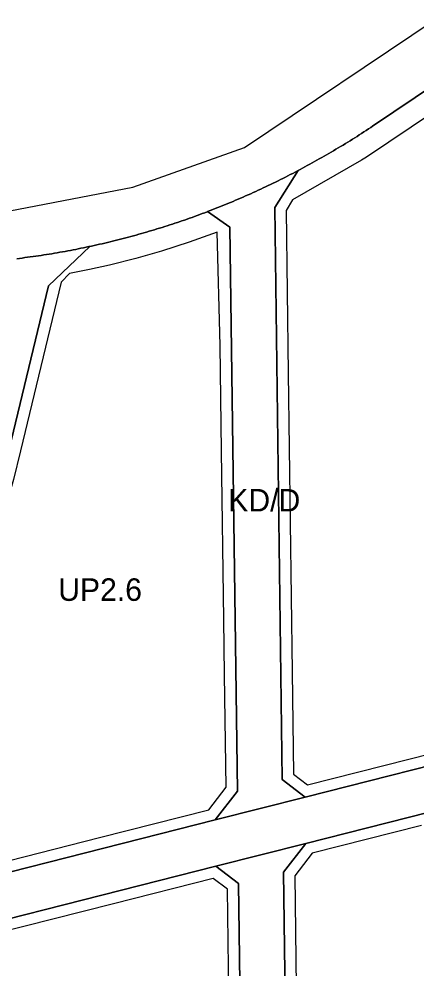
# Model space of a CAD drawing. Extents: x -297746 to -295403, y 27112 to 28877.
# Drawn here: x -296833.6 to -296657.1, y 27745.5 to 28167.1 of the extents above; entities that cross this region are included whole.
import ezdxf

# ---------------------------------------------------------------- set-up
doc = ezdxf.new("R2010")
doc.units = 0
for name, color, linetype in [('linie_rozgraniczajace', 7, 'Continuous'), ('linie_zabudowy_nieprzekraczalne', 7, 'Continuous'), ('oznaczenia_przeznaczen', 7, 'Continuous')]:
    doc.layers.add(name, color=color, linetype=linetype)

msp = doc.modelspace()

# ---------------------------------------------------------------- linework, layer by layer
at = {"layer": 'linie_rozgraniczajace'}
for points in [[(-297352.574, 28097.205), (-297275.154, 28075.397), (-297209.735, 28062.001), (-297116.494, 28056.361), (-297048.036, 28064.682), (-296954.075, 28076.102), (-296853.315, 28078.922), (-296783.197, 28092.318), (-296733.569, 28109.944), (-296648.599, 28167.051)], [(-296648.438, 28138.524), (-296676.764, 28119.432), (-296677.554, 28118.905), (-296678.571, 28118.231), (-296679.589, 28117.561), (-296680.61, 28116.894), (-296681.633, 28116.231), (-296682.659, 28115.57), (-296683.686, 28114.914), (-296684.716, 28114.26), (-296685.747, 28113.61), (-296686.781, 28112.963), (-296687.817, 28112.32), (-296688.855, 28111.68), (-296689.895, 28111.043), (-296690.938, 28110.41), (-296691.982, 28109.781), (-296693.028, 28109.154), (-296694.077, 28108.532), (-296695.127, 28107.912), (-296696.18, 28107.296), (-296697.234, 28106.684), (-296698.291, 28106.075), (-296699.349, 28105.469), (-296700.41, 28104.867), (-296701.472, 28104.269), (-296702.537, 28103.673), (-296703.603, 28103.082), (-296704.671, 28102.494), (-296705.742, 28101.909), (-296706.814, 28101.328), (-296707.888, 28100.751), (-296708.964, 28100.176), (-296709.827, 28099.719), (-296710.041, 28099.606), (-296711.121, 28099.039), (-296712.203, 28098.476), (-296713.286, 28097.916), (-296714.371, 28097.359), (-296715.458, 28096.807), (-296716.547, 28096.257), (-296717.638, 28095.712), (-296718.73, 28095.17), (-296719.824, 28094.631), (-296720.92, 28094.097), (-296722.018, 28093.565), (-296723.117, 28093.038), (-296724.218, 28092.514), (-296725.321, 28091.993), (-296726.426, 28091.476), (-296727.532, 28090.963), (-296728.64, 28090.454), (-296729.75, 28089.948), (-296730.861, 28089.445), (-296731.974, 28088.947), (-296733.088, 28088.452)], [(-296451.602, 27886.266), (-296706.72, 27821.429), (-296716.822, 27829.179), (-296720.16, 28083.326), (-296709.827, 28099.719), (-296708.964, 28100.176), (-296707.888, 28100.751), (-296706.814, 28101.328), (-296705.742, 28101.909), (-296704.671, 28102.494), (-296703.603, 28103.082), (-296702.537, 28103.673), (-296701.472, 28104.269), (-296700.41, 28104.867), (-296699.349, 28105.469), (-296698.291, 28106.075), (-296697.234, 28106.684), (-296696.18, 28107.296), (-296695.127, 28107.912), (-296694.077, 28108.532), (-296693.028, 28109.154), (-296691.982, 28109.781), (-296690.938, 28110.41), (-296689.895, 28111.043), (-296688.855, 28111.68), (-296687.817, 28112.32), (-296686.781, 28112.963), (-296685.747, 28113.61), (-296684.716, 28114.26), (-296683.686, 28114.914), (-296682.659, 28115.57), (-296681.633, 28116.231), (-296680.61, 28116.894), (-296679.589, 28117.561), (-296678.571, 28118.231), (-296677.554, 28118.905), (-296676.764, 28119.432), (-296648.438, 28138.524)], [(-296733.088, 28088.452), (-296734.204, 28087.961), (-296735.322, 28087.473), (-296736.441, 28086.989), (-296737.562, 28086.509), (-296738.685, 28086.032), (-296739.809, 28085.559), (-296740.934, 28085.09), (-296742.061, 28084.624), (-296743.19, 28084.162), (-296744.32, 28083.704), (-296745.452, 28083.25), (-296746.585, 28082.799), (-296747.72, 28082.352), (-296748.856, 28081.909), (-296749.993, 28081.469), (-296750.093, 28081.431), (-296751.216, 28081.007), (-296752.34, 28080.586), (-296753.465, 28080.169), (-296754.592, 28079.756), (-296755.72, 28079.347), (-296756.849, 28078.941), (-296757.98, 28078.539), (-296759.112, 28078.141), (-296760.245, 28077.747), (-296761.38, 28077.356), (-296762.164, 28077.089), (-296763.301, 28076.705), (-296764.439, 28076.324), (-296765.578, 28075.948), (-296766.719, 28075.575), (-296767.861, 28075.206), (-296769.004, 28074.841), (-296770.148, 28074.48), (-296771.293, 28074.122), (-296772.44, 28073.768), (-296773.588, 28073.419), (-296774.737, 28073.072), (-296775.887, 28072.73), (-296777.039, 28072.392), (-296778.191, 28072.057), (-296779.344, 28071.727), (-296780.499, 28071.4), (-296781.655, 28071.077), (-296782.812, 28070.758), (-296783.969, 28070.442), (-296785.128, 28070.131), (-296786.288, 28069.823), (-296787.449, 28069.52), (-296788.611, 28069.22), (-296789.774, 28068.924), (-296790.938, 28068.632), (-296792.103, 28068.344), (-296793.269, 28068.059), (-296794.435, 28067.779), (-296795.603, 28067.503), (-296796.772, 28067.23), (-296797.941, 28066.961), (-296799.112, 28066.696), (-296800.283, 28066.435), (-296801.455, 28066.178), (-296802.248, 28066.007), (-296802.628, 28065.925), (-296803.802, 28065.676), (-296804.977, 28065.431), (-296806.152, 28065.189), (-296807.328, 28064.952), (-296808.505, 28064.719), (-296809.683, 28064.489), (-296810.862, 28064.263), (-296812.041, 28064.041), (-296813.221, 28063.824), (-296814.402, 28063.61), (-296815.584, 28063.4), (-296816.766, 28063.194), (-296817.949, 28062.992), (-296819.132, 28062.794), (-296820.316, 28062.6), (-296821.501, 28062.409), (-296822.687, 28062.223), (-296823.873, 28062.041), (-296825.059, 28061.862), (-296826.247, 28061.688), (-296827.434, 28061.518), (-296828.623, 28061.351), (-296829.812, 28061.188), (-296831.001, 28061.03), (-296832.191, 28060.875), (-296833.382, 28060.725), (-296834.573, 28060.578)], [(-296840.945, 27963.7), (-296820.49, 28048.576), (-296802.248, 28066.007), (-296801.455, 28066.178), (-296800.283, 28066.435), (-296799.112, 28066.696), (-296797.941, 28066.961), (-296796.772, 28067.23), (-296795.603, 28067.503), (-296794.435, 28067.779), (-296793.269, 28068.059), (-296792.103, 28068.344), (-296790.938, 28068.632), (-296789.774, 28068.924), (-296788.611, 28069.22), (-296787.449, 28069.52), (-296786.288, 28069.823), (-296785.128, 28070.131), (-296783.969, 28070.442), (-296782.812, 28070.758), (-296781.655, 28071.077), (-296780.499, 28071.4), (-296779.344, 28071.727), (-296778.191, 28072.057), (-296777.039, 28072.392), (-296775.887, 28072.73), (-296774.737, 28073.072), (-296773.588, 28073.419), (-296772.44, 28073.768), (-296771.293, 28074.122), (-296770.148, 28074.48), (-296769.004, 28074.841), (-296767.861, 28075.206), (-296766.719, 28075.575), (-296765.578, 28075.948), (-296764.439, 28076.324), (-296763.301, 28076.705), (-296762.164, 28077.089), (-296761.38, 28077.356), (-296760.245, 28077.747), (-296759.112, 28078.141), (-296757.98, 28078.539), (-296756.849, 28078.941), (-296755.72, 28079.347), (-296754.592, 28079.756), (-296753.465, 28080.169), (-296752.34, 28080.586), (-296751.216, 28081.007), (-296750.093, 28081.431), (-296749.993, 28081.469), (-296740.047, 28074.586), (-296736.758, 27824.113), (-296746.59, 27811.296), (-296903.708, 27771.365)], [(-296834.573, 28060.578), (-296833.382, 28060.725), (-296832.191, 28060.875), (-296831.001, 28061.03), (-296829.812, 28061.188), (-296828.623, 28061.351), (-296827.434, 28061.518), (-296826.247, 28061.688), (-296825.059, 28061.862), (-296823.873, 28062.041), (-296822.687, 28062.223), (-296821.501, 28062.409), (-296820.316, 28062.6), (-296819.132, 28062.794), (-296817.949, 28062.992), (-296816.766, 28063.194), (-296815.584, 28063.4), (-296814.402, 28063.61), (-296813.221, 28063.824), (-296812.041, 28064.041), (-296810.862, 28064.263), (-296809.683, 28064.489), (-296808.505, 28064.719), (-296807.328, 28064.952), (-296806.152, 28065.189), (-296804.977, 28065.431), (-296803.802, 28065.676), (-296802.628, 28065.925), (-296802.248, 28066.007), (-296820.49, 28048.576), (-296840.945, 27963.7)], [(-297002.218, 27750.658), (-297000.74, 27748.463), (-296999.755, 27746.94), (-296998.73, 27747.216), (-296938.097, 27762.625), (-296922.224, 27766.659), (-296908.226, 27770.217), (-296903.708, 27771.365), (-296746.59, 27811.296), (-296706.72, 27821.429), (-296451.602, 27886.266)], [(-296434.505, 27869.975), (-296706.45, 27800.862), (-296746.32, 27790.729), (-296906.963, 27749.902), (-296939.511, 27741.63), (-296994.696, 27727.605), (-296995.426, 27722.859), (-296995.977, 27720.526), (-296996.722, 27717.999), (-296996.986, 27717.325), (-296988.793, 27710.975), (-297001.433, 27695.468), (-297009.248, 27701.525), (-297010.984, 27700.354), (-297012.53, 27699.459), (-297013.954, 27698.747), (-297015.744, 27697.933), (-297017.209, 27697.364), (-297018.714, 27696.855), (-297020.158, 27696.448), (-297021.212, 27696.201), (-297026.982, 27695.447)], [(-296732.893, 27529.874), (-296736.217, 27782.978), (-296746.32, 27790.729), (-296706.45, 27800.862), (-296716.282, 27788.045), (-296712.625, 27509.58)]]:
    msp.add_lwpolyline(points, dxfattribs=at)
for points in [[(-296746.59, 27811.296), (-296736.758, 27824.113), (-296740.047, 28074.586), (-296749.993, 28081.469), (-296748.856, 28081.909), (-296747.72, 28082.352), (-296746.585, 28082.799), (-296745.452, 28083.25), (-296744.32, 28083.704), (-296743.19, 28084.162), (-296742.061, 28084.624), (-296740.934, 28085.09), (-296739.809, 28085.559), (-296738.685, 28086.032), (-296737.562, 28086.509), (-296736.441, 28086.989), (-296735.322, 28087.473), (-296734.204, 28087.961), (-296733.088, 28088.452), (-296731.974, 28088.947), (-296730.861, 28089.445), (-296729.75, 28089.948), (-296728.64, 28090.454), (-296727.532, 28090.963), (-296726.426, 28091.476), (-296725.321, 28091.993), (-296724.218, 28092.514), (-296723.117, 28093.038), (-296722.018, 28093.565), (-296720.92, 28094.097), (-296719.824, 28094.631), (-296718.73, 28095.17), (-296717.638, 28095.712), (-296716.547, 28096.257), (-296715.458, 28096.807), (-296714.371, 28097.359), (-296713.286, 28097.916), (-296712.203, 28098.476), (-296711.121, 28099.039), (-296710.041, 28099.606), (-296709.827, 28099.719), (-296720.16, 28083.326), (-296716.822, 27829.179), (-296706.72, 27821.429)], [(-296708.605, 27498.319), (-296712.625, 27509.58), (-296716.282, 27788.045), (-296706.45, 27800.862), (-296434.505, 27869.975), (-296420.556, 27861.932), (-296445.171, 27819.646), (-296445.951, 27818.307), (-296482.154, 27756.115), (-296497.72, 27735.144)], [(-296746.434, 27523.132), (-296917.139, 27655.438), (-296926.254, 27679.375), (-296915.532, 27737.059), (-296906.963, 27749.902), (-296746.32, 27790.729), (-296736.217, 27782.978), (-296732.893, 27529.874)]]:
    msp.add_lwpolyline(points, close=True, dxfattribs=at)
at = {"layer": 'linie_zabudowy_nieprzekraczalne'}
for points in [[(-296649.741, 28125.587), (-296679.465, 28105.72), (-296681.763, 28104.411), (-296712.278, 28086.739), (-296715.138, 28081.914), (-296714.191, 28009.758), (-296712.447, 27877.015), (-296711.852, 27831.672), (-296705.598, 27826.874), (-296660.684, 27838.289), (-296525.454, 27872.657), (-296474.728, 27885.549), (-296454.954, 27890.574), (-296442.117, 27914.3), (-296453.116, 27925.493)], [(-296851.976, 27789.673), (-296824.597, 27796.631), (-296797.958, 27803.401), (-296749.499, 27815.717), (-296741.777, 27825.783), (-296742.434, 27875.778), (-296742.755, 27900.235), (-296743.74, 27975.234), (-296744.353, 28021.948), (-296745.685, 28072.411), (-296758.138, 28067.897), (-296770.384, 28063.942), (-296781.847, 28060.666), (-296793.481, 28057.73), (-296802.375, 28055.778), (-296811.307, 28054.009), (-296814.968, 28050.135), (-296833.03, 27975.191), (-296836.107, 27962.425), (-296842.232, 27941.104), (-296873.517, 27853.087), (-296883.689, 27824.469)], [(-296655.075, 27808.761), (-296703.535, 27796.445), (-296711.257, 27786.379), (-296710.61, 27737.164), (-296710.6, 27736.383), (-296707.633, 27510.479), (-296702.161, 27495.148), (-296673.896, 27473.241), (-296648.812, 27502.094)], [(-296873.104, 27627.639), (-296781.896, 27556.948), (-296755.716, 27536.657), (-296745.85, 27529.009), (-296737.931, 27532.952), (-296738.087, 27544.856), (-296738.528, 27578.409), (-296740.575, 27734.304), (-296741.182, 27780.49), (-296747.436, 27785.287), (-296791.663, 27774.047), (-296845.078, 27760.472)]]:
    msp.add_lwpolyline(points, dxfattribs=at)

# ---------------------------------------------------------------- texts
at = {"layer": 'oznaczenia_przeznaczen'}
for s, p in [('KD/D', (-296740.798, 27948.28)), ('UP2.6', (-296816.258, 27908.582))]:
    msp.add_text(s, height=10, dxfattribs=at).set_placement(p)

doc.saveas('drawing.dxf')
